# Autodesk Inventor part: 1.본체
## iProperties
Created: 2015-04
Part Number: 1.본체
Material: 알루미늄-6061
Document SubType Name: Modeling
Designer: elite
Mass: 450.554 g
Surface Area: 332.785 cm^2
Volume: 166.256 cm^3
Density: 2.71 g/cm^3
Author: elite
